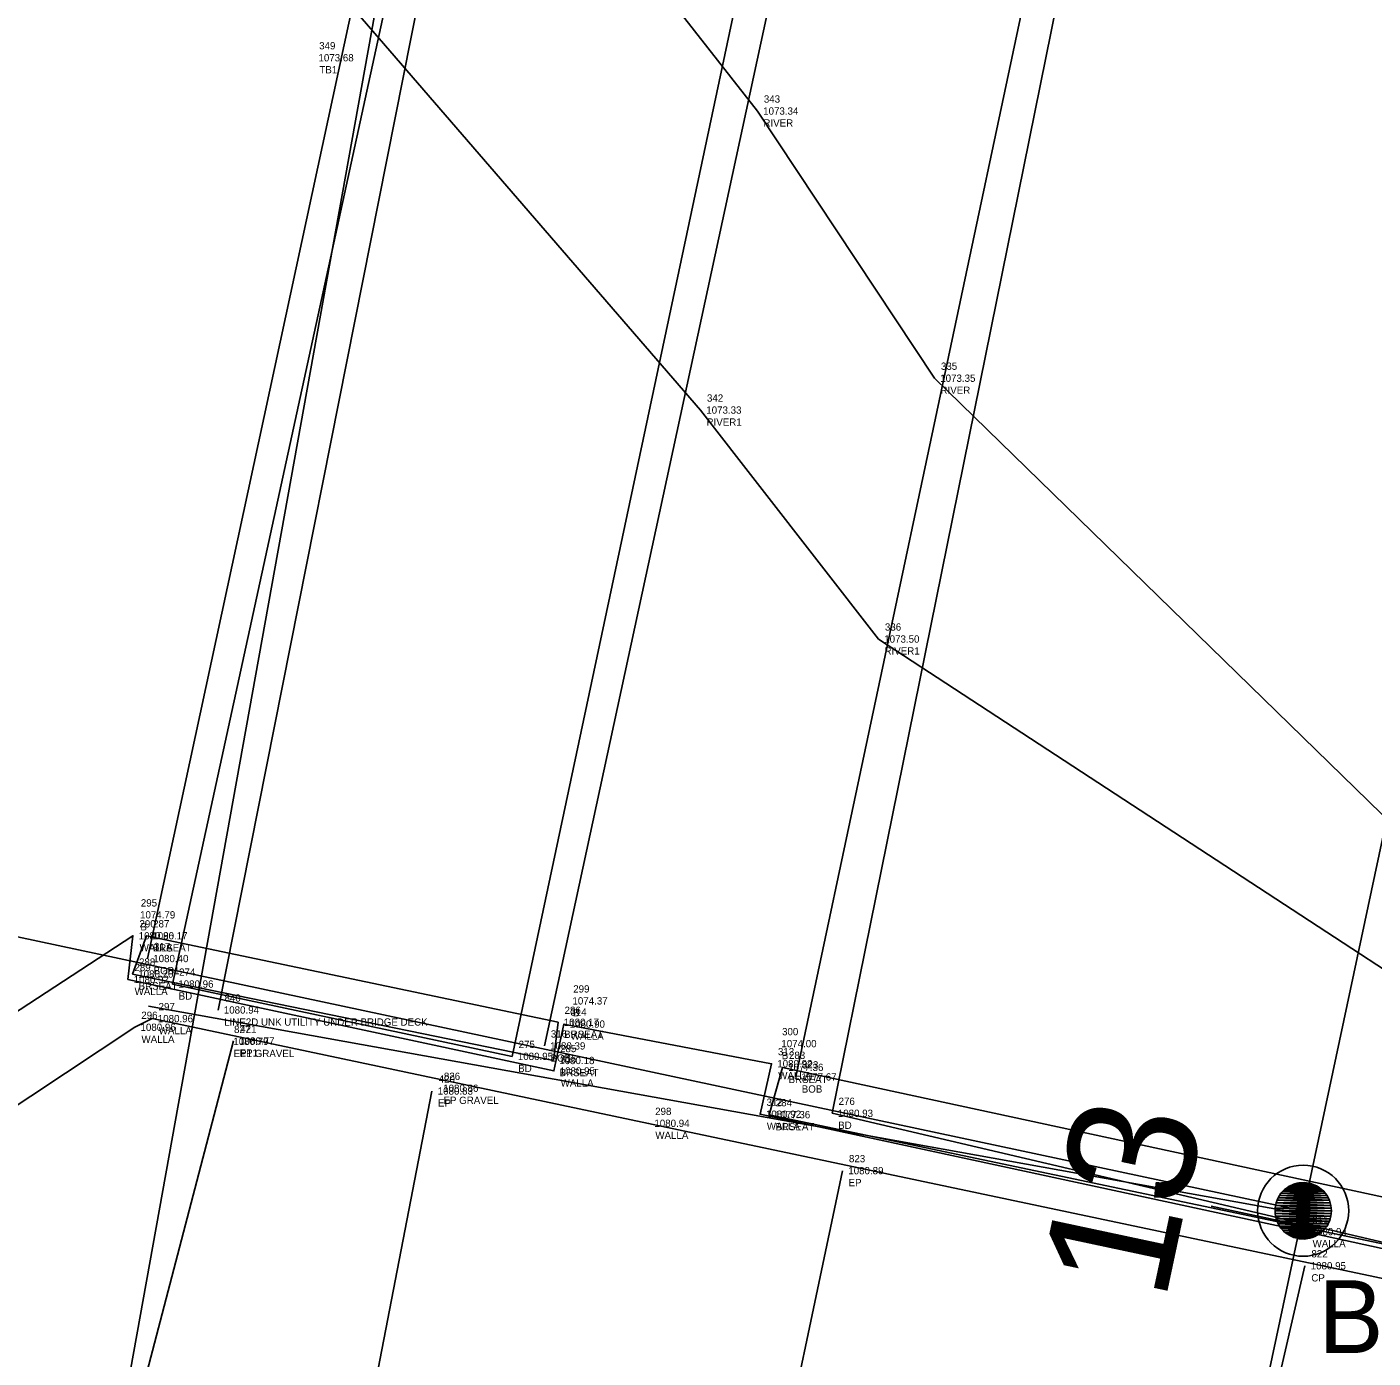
# Model space of a CAD drawing. Extents: x 2296145 to 2296886, y 654772 to 655516.
# Drawn here: x 2296396.47 to 2296426.05, y 655104.34 to 655133.59 of the extents above; entities that cross this region are included whole.
import ezdxf

# ---------------------------------------------------------------- set-up
doc = ezdxf.new("R2010")
doc.units = 0
for name, color, linetype in [('BR_X_SV_Abut', 7, 'Continuous'), ('BR_X_SV_Beam_Seat', 7, 'Continuous'), ('BR_X_SV_Bottom_of_Beam', 7, 'Continuous'), ('BR_X_SV_Deck_Top', 7, 'Continuous'), ('GE_P_CL', 7, 'Continuous'), ('GE_P_CL_20', 7, 'Continuous'), ('HY_X_Water_Edge', 7, 'Continuous'), ('PV_X_EOP', 7, 'Continuous'), ('SH_Text', 7, 'Continuous'), ('SV_P_Control_Cells_Set', 7, 'Continuous'), ('SV_X_Center_of_Pavt', 7, 'Continuous'), ('SV_X_Text_Comment', 7, 'Continuous'), ('SV_X_Text_Description', 7, 'Continuous'), ('UT_X_Telecom', 7, 'Continuous'), ('UT_X_Telecom_FO', 7, 'Continuous'), ('UT_X_Unknown_Cells', 7, 'Continuous')]:
    doc.layers.add(name, color=color, linetype=linetype)

msp = doc.modelspace()

# ---------------------------------------------------------------- linework, layer by layer
at = {"layer": 'BR_X_SV_Abut'}
msp.add_lwpolyline([(2296398.69, 655112.66), (2296398.8, 655113.62), (2296386.39, 655105.51), (2296387.43, 655104.05), (2296398.84, 655111.61), (2296399.22, 655111.8), (2296410.13, 655109.5), (2296435.31, 655104.18), (2296443.05, 655092.31), (2296444.57, 655093.33), (2296436.45, 655105.64), (2296436.14, 655104.59), (2296424.57, 655107.12), (2296412.58, 655109.7), (2296412.83, 655110.81), (2296408.27, 655111.68), (2296408.05, 655110.65), (2296398.69, 655112.66)], dxfattribs=at)
at = {"layer": 'BR_X_SV_Beam_Seat'}
for points in [[(2296408.04, 655110.88), (2296408.14, 655111.72), (2296399.1, 655113.62), (2296398.79, 655112.78), (2296408.04, 655110.88)], [(2296436.15, 655104.77), (2296436.32, 655105.71), (2296413.07, 655110.73), (2296412.78, 655109.69), (2296436.15, 655104.77)]]:
    msp.add_lwpolyline(points, dxfattribs=at)
at = {"layer": 'BR_X_SV_Bottom_of_Beam'}
for p, q in [((2296399.12, 655113.12), (2296405.46, 655142.57)), ((2296407.84, 655111.2), (2296414.24, 655140.84)), ((2296419.43, 655139.15), (2296413.36, 655110.52))]:
    msp.add_line(p, q, dxfattribs=at)
at = {"layer": 'BR_X_SV_Deck_Top'}
for points in [[(2296413.55, 655141.19), (2296406.25, 655142.82), (2296399.67, 655112.56), (2296407.13, 655110.97), (2296413.55, 655141.19)], [(2296414.16, 655109.72), (2296420.3, 655140.04), (2296441.54, 655135.42), (2296435.15, 655104.8), (2296414.16, 655109.72)]]:
    msp.add_lwpolyline(points, dxfattribs=at)
at = {"layer": 'GE_P_CL'}
msp.add_line((2296418.26, 655078.221), (2296466.082, 655302.878), dxfattribs=at)
msp.add_circle((2296424.51, 655107.58), 1, dxfattribs=at)
at = {"layer": 'GE_P_CL_20'}
msp.add_line((2296424.442, 655107.261), (2296422.486, 655107.678), dxfattribs=at)
at = {"layer": 'HY_X_Water_Edge'}
for points in [[(2296416.41, 655125.87), (2296412.52, 655131.74), (2296404.64, 655141.79), (2296402.07, 655141.47), (2296395.58, 655140.91), (2296385.63, 655136.09), (2296378.48, 655124.65), (2296372.29, 655124.31), (2296363.11, 655127.84), (2296354.84, 655138.19), (2296351.23, 655141), (2296332.78, 655150.33), (2296326.79, 655143.04), (2296307.58, 655141.27), (2296297.31, 655140.48), (2296289.3, 655139.85), (2296281.56, 655144.35), (2296268.07, 655155.94), (2296263.89, 655156.41), (2296215.99, 655162.35)], [(2296415.18, 655120.14), (2296411.27, 655125.17), (2296400.8, 655137.29), (2296391.12, 655135.23), (2296384.24, 655124.24), (2296377.53, 655121.68), (2296372.05, 655120.13), (2296365.56, 655120.36), (2296356, 655124), (2296351.48, 655132.49), (2296348.94, 655134.06), (2296337.35, 655144.97), (2296329.57, 655140.47), (2296323.4, 655136.11), (2296316.87, 655136.64), (2296306.21, 655134.29), (2296296.38, 655130.93), (2296277.37, 655140.88), (2296262.89, 655151.11), (2296244.69, 655152.89), (2296216.23, 655158.82)], [(2296416.41, 655125.87), (2296427.1, 655115.45), (2296438.88, 655113.75), (2296455.14, 655107.15), (2296470.14, 655110.14), (2296483.16, 655114.46), (2296505.87, 655117.72), (2296524.75, 655113.51), (2296529.66, 655112.86), (2296527.46, 655097.14), (2296527.77, 655091.65), (2296537.59, 655080.06), (2296547.88, 655070.84), (2296565.32, 655067.84), (2296572.93, 655070.08), (2296591.06, 655072.44), (2296602.66, 655064.53), (2296612.47, 655062.37)], [(2296415.18, 655120.14), (2296436.72, 655106.06), (2296440.43, 655107.12), (2296455.23, 655103.42), (2296466.38, 655103.34), (2296476.23, 655105.31), (2296484.61, 655110.23), (2296506.74, 655112.45), (2296523.97, 655109.66), (2296523.47, 655103.28), (2296521.32, 655098.85), (2296521.47, 655087.43), (2296530.274, 655073.763), (2296544.68, 655066.35), (2296555.12, 655060.29), (2296566.1, 655060.19), (2296573.18, 655065.46), (2296579.09, 655067.52), (2296583.65, 655067.14), (2296594.14, 655066.37), (2296601.39, 655060.67), (2296610.28, 655055.67)]]:
    msp.add_lwpolyline(points, dxfattribs=at)
at = {"layer": 'PV_X_EOP'}
for points in [[(2296377.26, 655059.47), (2296384.74, 655069.27), (2296394.67, 655088.28), (2296397.41, 655097.55), (2296401.01, 655111.31)], [(2296375.63, 655049.69), (2296388.99, 655067.76), (2296398.12, 655083.97), (2296402.75, 655096.68), (2296405.37, 655110.21)], [(2296404.15, 655059.98), (2296409.27, 655084.16), (2296414.39, 655108.46)]]:
    msp.add_lwpolyline(points, dxfattribs=at)
at = {"layer": 'SH_Text'}
msp.add_line((2296365.825, 655120.072), (2296424.51, 655107.58), dxfattribs=at)
at = {"layer": 'SV_P_Control_Cells_Set'}
for points in [[(2296424.022, 655107.964), (2296425.034, 655107.915), (2296423.991, 655107.915)], [(2296424.065, 655108.008), (2296424.996, 655107.964), (2296424.022, 655107.964)], [(2296424.022, 655107.964), (2296424.996, 655107.964), (2296425.034, 655107.915)], [(2296424.103, 655108.049), (2296424.961, 655108.008), (2296424.065, 655108.008)], [(2296424.065, 655108.008), (2296424.961, 655108.008), (2296424.996, 655107.964)], [(2296424.155, 655108.086), (2296424.913, 655108.049), (2296424.103, 655108.049)], [(2296424.103, 655108.049), (2296424.913, 655108.049), (2296424.961, 655108.008)], [(2296424.2, 655108.118), (2296424.871, 655108.086), (2296424.155, 655108.086)], [(2296424.155, 655108.086), (2296424.871, 655108.086), (2296424.913, 655108.049)], [(2296424.259, 655108.145), (2296424.816, 655108.118), (2296424.2, 655108.118)], [(2296424.2, 655108.118), (2296424.816, 655108.118), (2296424.871, 655108.086)], [(2296424.307, 655108.167), (2296424.769, 655108.145), (2296424.259, 655108.145)], [(2296424.259, 655108.145), (2296424.769, 655108.145), (2296424.816, 655108.118)], [(2296424.376, 655108.184), (2296424.705, 655108.167), (2296424.307, 655108.167)], [(2296424.307, 655108.167), (2296424.705, 655108.167), (2296424.769, 655108.145)], [(2296424.422, 655108.195), (2296424.657, 655108.184), (2296424.376, 655108.184)], [(2296424.376, 655108.184), (2296424.657, 655108.184), (2296424.705, 655108.167)], [(2296424.54, 655108.2), (2296424.579, 655108.195), (2296424.422, 655108.195)], [(2296424.422, 655108.195), (2296424.579, 655108.195), (2296424.657, 655108.184)], [(2296423.903, 655107.697), (2296425.127, 655107.638), (2296423.892, 655107.638)], [(2296423.914, 655107.754), (2296425.121, 655107.697), (2296423.903, 655107.697)], [(2296423.903, 655107.697), (2296425.121, 655107.697), (2296425.127, 655107.638)], [(2296423.936, 655107.81), (2296425.104, 655107.754), (2296423.914, 655107.754)], [(2296423.914, 655107.754), (2296425.104, 655107.754), (2296425.121, 655107.697)], [(2296423.958, 655107.864), (2296425.088, 655107.81), (2296423.936, 655107.81)], [(2296423.936, 655107.81), (2296425.088, 655107.81), (2296425.104, 655107.754)], [(2296423.991, 655107.915), (2296425.06, 655107.864), (2296423.958, 655107.864)], [(2296423.958, 655107.864), (2296425.06, 655107.864), (2296425.088, 655107.81)], [(2296423.991, 655107.915), (2296425.034, 655107.915), (2296425.06, 655107.864)], [(2296423.892, 655107.638), (2296425.132, 655107.579), (2296423.892, 655107.579)], [(2296423.892, 655107.638), (2296425.127, 655107.638), (2296425.132, 655107.579)], [(2296423.892, 655107.579), (2296425.127, 655107.52), (2296423.892, 655107.52)], [(2296423.892, 655107.579), (2296425.132, 655107.579), (2296425.127, 655107.52)], [(2296423.892, 655107.52), (2296425.121, 655107.462), (2296423.903, 655107.462)], [(2296423.892, 655107.52), (2296425.127, 655107.52), (2296425.121, 655107.462)], [(2296423.903, 655107.462), (2296425.104, 655107.404), (2296423.914, 655107.404)], [(2296423.903, 655107.462), (2296425.121, 655107.462), (2296425.104, 655107.404)], [(2296423.914, 655107.404), (2296425.088, 655107.348), (2296423.936, 655107.348)], [(2296423.914, 655107.404), (2296425.104, 655107.404), (2296425.088, 655107.348)], [(2296423.936, 655107.348), (2296425.06, 655107.294), (2296423.958, 655107.294)], [(2296423.936, 655107.348), (2296425.088, 655107.348), (2296425.06, 655107.294)], [(2296423.958, 655107.294), (2296425.034, 655107.243), (2296423.991, 655107.243)], [(2296423.958, 655107.294), (2296425.06, 655107.294), (2296425.034, 655107.243)], [(2296423.991, 655107.243), (2296424.996, 655107.195), (2296424.022, 655107.195)], [(2296423.991, 655107.243), (2296425.034, 655107.243), (2296424.996, 655107.195)], [(2296424.022, 655107.195), (2296424.961, 655107.15), (2296424.065, 655107.15)], [(2296424.022, 655107.195), (2296424.996, 655107.195), (2296424.961, 655107.15)], [(2296424.065, 655107.15), (2296424.913, 655107.109), (2296424.103, 655107.109)], [(2296424.065, 655107.15), (2296424.961, 655107.15), (2296424.913, 655107.109)], [(2296424.103, 655107.109), (2296424.871, 655107.073), (2296424.155, 655107.073)], [(2296424.103, 655107.109), (2296424.913, 655107.109), (2296424.871, 655107.073)], [(2296424.155, 655107.073), (2296424.816, 655107.041), (2296424.2, 655107.041)], [(2296424.155, 655107.073), (2296424.871, 655107.073), (2296424.816, 655107.041)], [(2296424.2, 655107.041), (2296424.769, 655107.014), (2296424.259, 655107.014)], [(2296424.2, 655107.041), (2296424.816, 655107.041), (2296424.769, 655107.014)], [(2296424.259, 655107.014), (2296424.705, 655106.992), (2296424.307, 655106.992)], [(2296424.259, 655107.014), (2296424.769, 655107.014), (2296424.705, 655106.992)], [(2296424.307, 655106.992), (2296424.657, 655106.975), (2296424.376, 655106.975)], [(2296424.307, 655106.992), (2296424.705, 655106.992), (2296424.657, 655106.975)], [(2296424.376, 655106.975), (2296424.579, 655106.964), (2296424.422, 655106.964)], [(2296424.376, 655106.975), (2296424.657, 655106.975), (2296424.579, 655106.964)], [(2296424.422, 655106.964), (2296424.579, 655106.964), (2296424.54, 655106.958)]]:
    msp.add_lwpolyline(points, close=True, dxfattribs=at)
at = {"layer": 'SV_X_Center_of_Pavt'}
msp.add_lwpolyline([(2296414.51, 655057.99), (2296419.05, 655082.48), (2296424.55, 655106.37)], dxfattribs=at)
at = {"layer": 'UT_X_Telecom'}
msp.add_lwpolyline([(2296442.618, 654772.147), (2296420.05, 654875.802), (2296396.714, 655002.693), (2296392.966, 655039.593), (2296397.411, 655096.654), (2296407.58, 655153.112), (2296425.032, 655215.218), (2296459.312, 655292.318), (2296480.856, 655335.072), (2296534.163, 655440.86), (2296557.466, 655508.866)], dxfattribs=at)
at = {"layer": 'UT_X_Telecom_FO'}
msp.add_line((2296424.495, 655107.509), (2296399.143, 655112.075), dxfattribs=at)
at = {"layer": 'UT_X_Unknown_Cells'}
msp.add_line((2296400.67, 655111.99), (2296406.84, 655143.09), dxfattribs=at)

# ---------------------------------------------------------------- texts
at = {"layer": 'GE_P_CL_20'}
msp.add_text('13', height=2.8, rotation=77.983, dxfattribs=at).set_placement((2296421.47, 655105.543))
at = {"layer": 'SV_X_Text_Comment'}
for s, p in [('349', (2296402.891, 655133.095)), ('1073.68', (2296402.876, 655132.831)), ('TB1', (2296402.895, 655132.568)), ('343', (2296412.661, 655131.925)), ('1073.34', (2296412.646, 655131.661)), ('RIVER', (2296412.652, 655131.398)), ('335', (2296416.551, 655126.055)), ('1073.35', (2296416.536, 655125.791)), ('RIVER', (2296416.542, 655125.528)), ('342', (2296411.411, 655125.355)), ('1073.33', (2296411.396, 655125.091)), ('RIVER1', (2296411.402, 655124.828)), ('336', (2296415.321, 655120.325)), ('1073.50', (2296415.306, 655120.061)), ('RIVER1', (2296415.312, 655119.798)), ('1074.79', (2296398.956, 655114.001)), ('295', (2296398.973, 655114.264)), ('290', (2296398.943, 655113.804)), ('B', (2296398.964, 655113.738)), ('287', (2296399.243, 655113.804)), ('1080.96', (2296398.926, 655113.541)), ('1080.17', (2296399.226, 655113.541)), ('WALLA', (2296398.947, 655113.278)), ('BRSEAT', (2296399.234, 655113.276)), ('317', (2296399.261, 655113.305)), ('289', (2296398.833, 655112.844)), ('288', (2296398.933, 655112.964)), ('1080.40', (2296399.246, 655113.041)), ('1080.92', (2296398.816, 655112.581)), ('1080.20', (2296398.916, 655112.701)), ('BOB1', (2296399.254, 655112.775)), ('274', (2296399.813, 655112.742)), ('WALLA', (2296398.837, 655112.318)), ('BRSEAT', (2296398.924, 655112.436)), ('1080.96', (2296399.796, 655112.481)), ('BD', (2296399.804, 655112.218)), ('299', (2296408.473, 655112.374)), ('297', (2296399.363, 655111.984)), ('840', (2296400.811, 655112.174)), ('1074.37', (2296408.456, 655112.111)), ('296', (2296398.983, 655111.794)), ('1080.96', (2296399.346, 655111.721)), ('1080.94', (2296400.796, 655111.911)), ('LINE2D UNK UTILITY UNDER BRIDGE DECK', (2296400.804, 655111.646)), ('1080.17', (2296408.266, 655111.641)), ('286', (2296408.283, 655111.904)), ('314', (2296408.411, 655111.865)), ('B', (2296408.464, 655111.848)), ('1080.96', (2296398.966, 655111.531)), ('WALLA', (2296399.367, 655111.458)), ('827', (2296401.021, 655111.484)), ('421', (2296401.157, 655111.492)), ('316', (2296407.981, 655111.385)), ('BRSEAT', (2296408.274, 655111.376)), ('1080.90', (2296408.396, 655111.601)), ('WALLA', (2296408.417, 655111.338)), ('300', (2296413.061, 655111.435)), ('WALLA', (2296398.987, 655111.268)), ('1080.79', (2296401.006, 655111.221)), ('1080.77', (2296401.136, 655111.231)), ('275', (2296407.273, 655111.154)), ('1080.39', (2296407.966, 655111.121)), ('285', (2296408.183, 655111.064)), ('1074.00', (2296413.046, 655111.171)), ('EP1 GRAVEL', (2296401.012, 655110.956)), ('EP1', (2296401.142, 655110.968)), ('1080.95', (2296407.256, 655110.891)), ('BOB', (2296407.974, 655110.855)), ('1080.18', (2296408.166, 655110.801)), ('315', (2296408.191, 655110.835)), ('313', (2296412.971, 655110.995)), ('B', (2296413.054, 655110.908)), ('283', (2296413.213, 655110.915)), ('826', (2296405.631, 655110.454)), ('BD', (2296407.264, 655110.628)), ('BRSEAT', (2296408.174, 655110.536)), ('1080.95', (2296408.176, 655110.571)), ('1080.92', (2296412.956, 655110.731)), ('WALLA', (2296412.977, 655110.468)), ('1077.36', (2296413.196, 655110.651)), ('1077.67', (2296413.486, 655110.441)), ('323', (2296413.501, 655110.705)), ('420', (2296405.517, 655110.394)), ('1080.86', (2296405.616, 655110.191)), ('WALLA', (2296408.197, 655110.308)), ('BRSEAT', (2296413.204, 655110.386)), ('BOB', (2296413.494, 655110.175)), ('1080.83', (2296405.496, 655110.131)), ('EP', (2296405.502, 655109.868)), ('EP GRAVEL', (2296405.622, 655109.926)), ('312', (2296412.721, 655109.885)), ('284', (2296412.923, 655109.874)), ('276', (2296414.303, 655109.904)), ('298', (2296410.273, 655109.684)), ('1080.92', (2296412.706, 655109.621)), ('1077.36', (2296412.906, 655109.611)), ('1080.93', (2296414.286, 655109.641)), ('1080.94', (2296410.256, 655109.421)), ('WALLA', (2296412.727, 655109.358)), ('BRSEAT', (2296412.914, 655109.346)), ('BD', (2296414.294, 655109.378)), ('WALLA', (2296410.277, 655109.158)), ('1080.89', (2296414.516, 655108.381)), ('823', (2296414.531, 655108.645)), ('EP', (2296414.522, 655108.118)), ('311', (2296424.711, 655107.305)), ('1080.94', (2296424.696, 655107.041)), ('WALLA', (2296424.717, 655106.778)), ('822', (2296424.691, 655106.554)), ('1080.95', (2296424.676, 655106.291)), ('CP', (2296424.689, 655106.026))]:
    msp.add_text(s, height=0.16, dxfattribs=at).set_placement(p)
at = {"layer": 'SV_X_Text_Description'}
msp.add_text('BRIDGE SPLIT', height=1.6, dxfattribs=at).set_placement((2296424.846, 655104.453))

doc.saveas('drawing.dxf')
